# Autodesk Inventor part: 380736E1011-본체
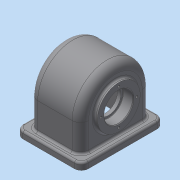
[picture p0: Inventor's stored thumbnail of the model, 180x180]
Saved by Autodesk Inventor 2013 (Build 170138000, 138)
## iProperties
Created: 2018-07
Part Number: 380736E1011-본체
Material: 1
Document SubType Name: Modeling
Designer: 05-01
Density: 7 g/cm^3
Mass: 2302.09 g
Surface Area: 764.976 cm^2
Volume: 328.87 cm^3
Author: 05-01
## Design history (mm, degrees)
sketch "스케치1"
  geometry: L1 (-60, 0)-(60, 0); L2 (60, 0)-(60, 10); L3 (60, 10)-(-60, 10); L4 (-60, 10)-(-60, 0); L5 (-51, 10)-(-51, 50); L6 (51, 50)-(51, 10); A1 r 51 centre (0, 50) between (51, 50) and (-51, 50); 2 further points
  constraints: 12 end point, 3 parallel, 2 perpendicular, 2 point on circle, 2 point on line, 2 tangent, 1 centre point, 1 coincident, 1 horizontal, 1 midpoint, 1 vertical alignment
  dimensions: "d0" = 10 distance of L1.end L2.end; "d2" = 120 distance of L1.start L1.end; "d3" = 51 radius of A1; "d4" = 50 distance from line of A1.centre L1
extrude "돌출1" new body sketch "스케치1" stored distance "d5" = 74; taper "d6" = 0 deg
extrude "돌출2" join sketch "스케치1" stored distance "d7" = 95; taper "d8" = 0 deg
fillet "모깎기1" dims "d9" = 12
feature "쉘1" dims "d10" = 10, "d11" = 9
sketch "스케치2"
  geometry: C1 r 31 at (-50, 0); A1 r 39 centre (-50, 0) between (-50, 39) and (-50, -39) reference; 1 further point
  constraints: 1 centre point, 1 coincident
  dimensions: "d12" = 62 diameter of C1
extrude "돌출3" join sketch "스케치2" distance "d14" = 5; taper "d16" = 0 deg; dims "d15" = 15, "d17" = 0
hole "구멍1" diameter "d20" = 36; stored, may be unused: countersink angle "d24" = 90 deg, drill point angle "d26" = 118 deg; dims "d18" = 10, "d19" = 10, "d21" = 6, "d22" = 42, "d23" = 15, "d25" = 8
sketch "스케치3"
  geometry: C1 r 21 at (0, 0) reference; 2 further points
  constraints: 1 horizontal alignment
  dimensions: "d27" = 26 distance of point (-26, 0) C1.centre
hole "구멍2" sketch "스케치3" at (-26, 0) diameter "d28" = 3.242; stored, may be unused: countersink angle "d32" = 90 deg, drill point angle "d34" = 118 deg; dims "d29" = 8, "d30" = 42, "d31" = 15, "d33" = 10
chamfer "모따기1" distance "d38" = 1; stored, may be unused: second distance "d39" = 2, angle "d40" = 45 deg
fillet "모깎기2" dims "d41" = 0.6
fillet "모깎기3" dims "d42" = 10
fillet "모깎기4" dims "d43" = 3
node "솔리드1"
mirror "대칭1"
pattern_circular "원형 패턴1" dims angle "d36" = 360 deg
mirror "대칭2"
